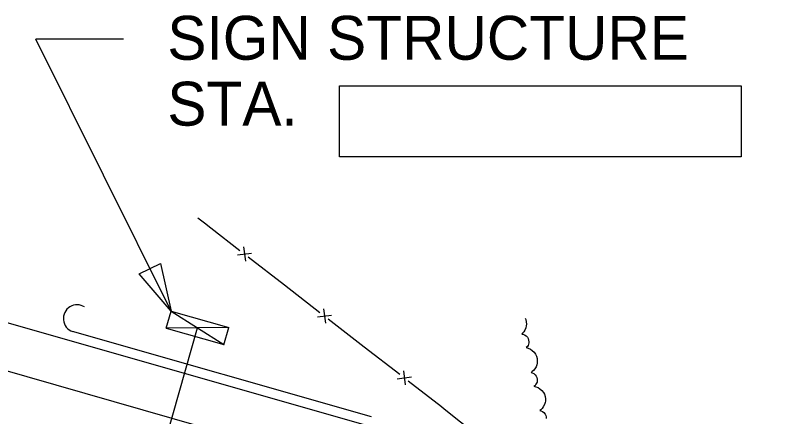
# Model space of a CAD drawing. Extents: x 3831399 to 3833095, y 499014 to 500202.
# Drawn here: x 3832674.1 to 3832726, y 499693.7 to 499721.1 of the extents above; entities that cross this region are included whole.
import ezdxf

# ---------------------------------------------------------------- set-up
doc = ezdxf.new("R2010")
doc.units = 0
for name, color, linetype in [('DIM TXT', 7, 'Continuous'), ('Level 10', 7, 'Continuous'), ('Level 2', 7, 'Continuous'), ('Level 20', 7, 'Continuous'), ('Level 21', 7, 'Continuous'), ('Level 26', 7, 'Continuous'), ('Level 27', 7, 'Continuous'), ('Level 43', 7, 'Continuous')]:
    doc.layers.add(name, color=color, linetype=linetype)

msp = doc.modelspace()

# ---------------------------------------------------------------- linework, layer by layer
at = {"layer": 'DIM TXT'}
for p in [(3832684.801, 499700.881), (3832681.56, 499719.459)]:
    msp.add_line(p, (3832675.56, 499719.459), dxfattribs=at)
msp.add_lwpolyline([(3832684.083, 499704.143), (3832684.801, 499700.881), (3832682.633, 499703.421)], close=True, dxfattribs=at)
at = {"layer": 'Level 2'}
for p, q in [((3832696.31, 499716.263), (3832723.777, 499716.263)), ((3832696.31, 499711.429), (3832696.31, 499716.263)), ((3832723.777, 499716.263), (3832723.777, 499711.429)), ((3832723.777, 499711.429), (3832696.31, 499711.429))]:
    msp.add_line(p, q, dxfattribs=at)
at = {"layer": 'Level 20'}
for p, q in [((3832709.009, 499700.406), (3832709.049, 499700.303)), ((3832709.049, 499700.303), (3832709.087, 499700.149)), ((3832709.059, 499699.74), (3832708.997, 499699.589)), ((3832709.092, 499699.886), (3832709.059, 499699.74)), ((3832709.087, 499700.149), (3832709.104, 499699.996)), ((3832709.104, 499699.996), (3832709.092, 499699.886)), ((3832708.841, 499699.371), (3832708.78, 499699.311)), ((3832708.78, 499699.311), (3832708.864, 499699.303)), ((3832708.921, 499699.466), (3832708.841, 499699.371)), ((3832708.864, 499699.303), (3832708.977, 499699.258)), ((3832708.997, 499699.589), (3832708.921, 499699.466)), ((3832708.977, 499699.258), (3832709.084, 499699.188)), ((3832709.084, 499699.188), (3832709.165, 499699.095)), ((3832709.165, 499699.095), (3832709.216, 499699.006)), ((3832709.27, 499698.707), (3832709.213, 499698.544)), ((3832709.216, 499699.006), (3832709.251, 499698.904)), ((3832709.251, 499698.904), (3832709.276, 499698.792)), ((3832709.276, 499698.792), (3832709.27, 499698.707)), ((3832709.09, 499698.39), (3832709.225, 499698.354)), ((3832709.17, 499698.461), (3832709.092, 499698.39)), ((3832709.213, 499698.544), (3832709.17, 499698.461)), ((3832709.225, 499698.354), (3832709.381, 499698.284)), ((3832709.381, 499698.284), (3832709.498, 499698.199)), ((3832709.498, 499698.199), (3832709.626, 499698.073)), ((3832709.626, 499698.073), (3832709.725, 499697.933)), ((3832709.725, 499697.933), (3832709.786, 499697.798)), ((3832709.786, 499697.798), (3832709.824, 499697.638)), ((3832709.81, 499697.224), (3832709.756, 499697.083)), ((3832709.837, 499697.33), (3832709.81, 499697.224)), ((3832709.824, 499697.638), (3832709.842, 499697.483)), ((3832709.842, 499697.483), (3832709.837, 499697.33)), ((3832709.491, 499696.747), (3832709.423, 499696.7)), ((3832709.423, 499696.7), (3832709.504, 499696.678)), ((3832709.583, 499696.833), (3832709.491, 499696.747)), ((3832709.504, 499696.678), (3832709.612, 499696.619)), ((3832709.675, 499696.943), (3832709.583, 499696.833)), ((3832709.612, 499696.619), (3832709.707, 499696.536)), ((3832709.756, 499697.083), (3832709.675, 499696.943)), ((3832709.707, 499696.536), (3832709.774, 499696.435)), ((3832709.774, 499696.435), (3832709.815, 499696.34)), ((3832709.815, 499696.34), (3832709.833, 499696.234)), ((3832709.842, 499696.12), (3832709.826, 499696.039)), ((3832709.833, 499696.234), (3832709.842, 499696.12)), ((3832709.693, 499695.809), (3832709.608, 499695.748)), ((3832709.608, 499695.748), (3832709.743, 499695.721)), ((3832709.747, 499695.883), (3832709.693, 499695.809)), ((3832709.743, 499695.721), (3832709.9, 499695.661)), ((3832709.826, 499696.039), (3832709.747, 499695.883)), ((3832709.9, 499695.661), (3832710.022, 499695.58)), ((3832710.022, 499695.58), (3832710.152, 499695.46)), ((3832710.152, 499695.46), (3832710.26, 499695.328)), ((3832710.26, 499695.328), (3832710.328, 499695.202)), ((3832710.328, 499695.202), (3832710.371, 499695.044)), ((3832710.375, 499694.635), (3832710.328, 499694.493)), ((3832710.371, 499695.044), (3832710.393, 499694.891)), ((3832710.395, 499694.74), (3832710.375, 499694.635)), ((3832710.393, 499694.891), (3832710.395, 499694.74)), ((3832710.076, 499694.149), (3832710.008, 499694.097)), ((3832710.008, 499694.097), (3832710.092, 499694.081)), ((3832710.166, 499694.234), (3832710.076, 499694.149)), ((3832710.092, 499694.081), (3832710.202, 499694.027)), ((3832710.251, 499694.351), (3832710.166, 499694.234)), ((3832710.202, 499694.027), (3832710.301, 499693.951)), ((3832710.328, 499694.493), (3832710.251, 499694.351)), ((3832710.301, 499693.951), (3832710.373, 499693.854)), ((3832710.373, 499693.854), (3832710.418, 499693.762)), ((3832710.418, 499693.762), (3832710.44, 499693.663)), ((3832710.44, 499693.663), (3832710.456, 499693.548))]:
    msp.add_line(p, q, dxfattribs=at)
at = {"layer": 'Level 21'}
for p, q in [((3832686.641, 499707.262), (3832687.096, 499706.904)), ((3832687.094, 499706.904), (3832687.526, 499706.56)), ((3832687.526, 499706.56), (3832689.513, 499705.023)), ((3832689.767, 499705.264), (3832689.891, 499704.294)), ((3832689.344, 499704.719), (3832690.314, 499704.841)), ((3832690.082, 499704.584), (3832692.553, 499702.669)), ((3832692.553, 499702.669), (3832694.976, 499700.795)), ((3832695.228, 499701.036), (3832695.352, 499700.066)), ((3832694.807, 499700.491), (3832695.775, 499700.615)), ((3832695.545, 499700.354), (3832698.016, 499698.442)), ((3832698.016, 499698.442), (3832700.437, 499696.567)), ((3832700.691, 499696.808), (3832700.813, 499695.838)), ((3832700.268, 499696.259), (3832701.236, 499696.385)), ((3832701.004, 499696.126), (3832703.294, 499694.356)), ((3832703.294, 499694.356), (3832703.474, 499694.212)), ((3832703.474, 499694.212), (3832705.873, 499692.306))]:
    msp.add_line(p, q, dxfattribs=at)
at = {"layer": 'Level 26'}
for p, q in [((3832651.141, 499706.5), (3832702.584, 499691.841)), ((3832650.267, 499703.432), (3832726.015, 499681.848))]:
    msp.add_line(p, q, dxfattribs=at)
at = {"layer": 'Level 27'}
msp.add_line((3832698.515, 499693.663), (3832678.063, 499699.49), dxfattribs=at)
msp.add_ellipse((3832678.385, 499700.375), major_axis=(0.538, 0.772), ratio=0.999995, start_param=0.035909, end_param=3.402363, dxfattribs=at)
at = {"layer": 'Level 43'}
for p, q in [((3832684.469, 499699.715), (3832684.802, 499700.881)), ((3832684.801, 499700.881), (3832688.747, 499699.757)), ((3832684.801, 499700.881), (3832688.415, 499698.591)), ((3832676.981, 499665.947), (3832686.608, 499699.738)), ((3832688.747, 499699.757), (3832684.47, 499699.715)), ((3832688.415, 499698.59), (3832688.746, 499699.756)), ((3832684.47, 499699.715), (3832688.415, 499698.591))]:
    msp.add_line(p, q, dxfattribs=at)

# ---------------------------------------------------------------- texts
at = {"layer": 'Level 10'}
for s, height, p in [('SIGN STRUCTURE', 2.99991, (3832684.55, 499718.052)), ('STA.', 2.9999, (3832684.55, 499713.552))]:
    msp.add_text(s, height=height, dxfattribs=at).set_placement(p)

doc.saveas('drawing.dxf')
